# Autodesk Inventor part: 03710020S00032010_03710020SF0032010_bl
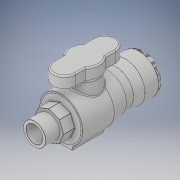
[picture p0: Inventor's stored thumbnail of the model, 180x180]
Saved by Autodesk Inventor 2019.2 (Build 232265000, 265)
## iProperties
Created: 2022-04
Part Number: 03710020S00032010_03710020SF0032010_bl
Material: Generic
Description: PA Ball Valve Series 1 32mm x Male 1''
Document SubType Name: Modeling
Designer: Lenora
Density: 1 g/cm^3
Appearance: Default
Author: Lenora
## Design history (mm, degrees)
derived "0371002.ipt"
feature "Solid1::0371002.ipt" dims "ScaleForDerivedMember" = 10
tag "TaggingFeature1"
body "Solid1"
other parameters: "d0" = 165 [user parameter], "d16" = 90.75 [user parameter], "d19" = 1 [user parameter], "d20" = 41.25 [user parameter], "d22" = 85 deg [user parameter], "d25" = 1 [user parameter], "d34" = 29.7 [user parameter], "d35" = 16.5 [user parameter], "d37" = 0 [user parameter], "d39" = 360 deg [user parameter], "d43" = 33 [user parameter], "d45" = 70 deg [user parameter], "d46" = 70 deg [user parameter], "d48" = 0 [user parameter], "d57" = 2 [user parameter], "d60" = 25 [user parameter], "d63" = 64 [user parameter], "d71" = 8.25 [user parameter], "d72" = 12.375 [user parameter], "d73" = 29.7 [user parameter], "d76" = 64 [user parameter], "d77" = 19.2 [user parameter], "d78" = 44.55 [user parameter], "d79" = 20.625 [user parameter], "d80" = 100 deg [user parameter], "d81" = 14.025 [user parameter], "d83" = 28.05 [user parameter], "d84" = 12.375 [user parameter], "d85" = 32 [user parameter], "d90" = 0 [user parameter], "d91" = 9.6 [user parameter], "d92" = 45 deg [user parameter], "d93" = 5.12 [user parameter], "d94" = 2.048 [user parameter], "d95" = 2.56 [user parameter], "d96" = 2.56 [user parameter], "d97" = 2.56 [user parameter], "d98" = 2.56 [user parameter], "d111" = 0.5 [user parameter], "d112" = 2 [user parameter], "d114" = 8.96 [user parameter], "d115" = 0 [user parameter], "d117" = 360 deg [user parameter], "d119" = 51.84 [user parameter], "d120" = 58 [user parameter], "d121" = 32 [user parameter], "d122" = 1 [user parameter], "d123" = 89 deg [user parameter], "d124" = 80 deg [user parameter], "d125" = 41 [user parameter], "d126" = 21 [user parameter], "d127" = 16.8 [user parameter], "d129" = 33.249 [user parameter], "d130" = 21.25 [user parameter], "d131" = 25 [user parameter], "d132" = 59.52 [user parameter], "d134" = 0 [user parameter], "d135" = 0.25 [user parameter], "d" = 32 [user parameter], "DN" = 25 [user parameter], "A1" = 33 [user parameter], "A2" = 64 [user parameter], "H_" = 165 [user parameter], "E_" = 64 [user parameter], "E1" = 58 [user parameter], "B" = 41 [user parameter], "l2" = 21 [user parameter], "R" = 33.249 [user parameter]
